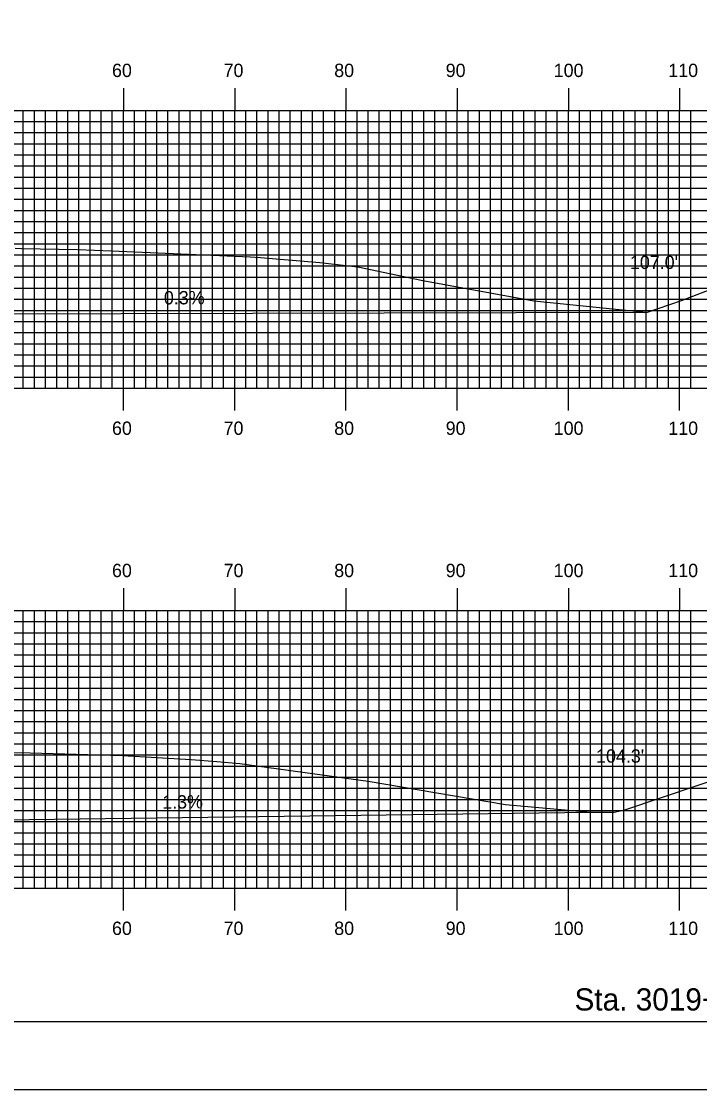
# Model space of a CAD drawing. Extents: x 1685979 to 1686323, y 461260 to 461480.
# Drawn here: x 1686196.1 to 1686257.1, y 461260 to 461356.1 of the extents above; entities that cross this region are included whole.
import ezdxf

# ---------------------------------------------------------------- set-up
doc = ezdxf.new("R2010")
doc.units = 0
for name, color, linetype in [('ANNOTATION', 7, 'Continuous'), ('BORDER', 7, 'Continuous'), ('D_Roadway_SlopeLines', 7, 'Continuous'), ('D_Text_Standard', 7, 'Continuous'), ('H_V ANNOTATION', 7, 'Continuous'), ('MAJOR', 7, 'Continuous'), ('MINOR', 7, 'Continuous'), ('PLOT BOUNDARY', 7, 'Continuous'), ('S_Roadway_Centerline', 7, 'Continuous')]:
    doc.layers.add(name, color=color, linetype=linetype)

msp = doc.modelspace()

# ---------------------------------------------------------------- linework, layer by layer
at = {"layer": 'BORDER'}
msp.add_lwpolyline([(1685995.656, 461266.072), (1686315.656, 461266.072), (1686315.656, 461476.072), (1685995.656, 461476.072)], close=True, dxfattribs=at)
at = {"layer": 'D_Roadway_SlopeLines'}
for points in [[(1686169.511, 461329.71), (1686252.38, 461329.925)], [(1686169.511, 461329.71), (1686252.38, 461329.925)], [(1686169.511, 461329.71), (1686252.38, 461329.925)], [(1686169.511, 461329.71), (1686252.38, 461329.925)], [(1686171.511, 461283.946), (1686249.53, 461284.948)], [(1686171.511, 461283.946), (1686249.53, 461284.948)], [(1686171.511, 461283.946), (1686249.53, 461284.948)], [(1686171.511, 461283.946), (1686249.53, 461284.948)]]:
    msp.add_lwpolyline(points, dxfattribs=at)
at = {"layer": 'MAJOR'}
for p, q in [((1686205.256, 461350.076), (1686205.256, 461348.072)), ((1686215.256, 461350.076), (1686215.256, 461348.072)), ((1686225.256, 461350.076), (1686225.256, 461348.072)), ((1686235.256, 461350.076), (1686235.256, 461348.072)), ((1686245.256, 461350.076), (1686245.256, 461348.072)), ((1686255.256, 461350.076), (1686255.256, 461348.072)), ((1686005.256, 461348.072), (1686285.256, 461348.072)), ((1686005.256, 461348.072), (1686285.256, 461348.072)), ((1686205.256, 461323.072), (1686205.256, 461348.072)), ((1686215.256, 461323.072), (1686215.256, 461348.072)), ((1686225.256, 461323.072), (1686225.256, 461348.072)), ((1686235.256, 461323.072), (1686235.256, 461348.072)), ((1686245.256, 461323.072), (1686245.256, 461348.072)), ((1686255.256, 461323.072), (1686255.256, 461348.072)), ((1686005.256, 461343.072), (1686285.256, 461343.072)), ((1686005.256, 461338.072), (1686285.256, 461338.072)), ((1686005.256, 461333.072), (1686285.256, 461333.072)), ((1686005.256, 461328.072), (1686285.256, 461328.072)), ((1686005.256, 461323.072), (1686285.256, 461323.072)), ((1686005.256, 461323.072), (1686285.256, 461323.072)), ((1686205.256, 461321.068), (1686205.256, 461323.072)), ((1686215.256, 461321.068), (1686215.256, 461323.072)), ((1686225.256, 461321.068), (1686225.256, 461323.072)), ((1686235.256, 461321.068), (1686235.256, 461323.072)), ((1686245.256, 461321.068), (1686245.256, 461323.072)), ((1686255.256, 461321.068), (1686255.256, 461323.072)), ((1686205.256, 461305.076), (1686205.256, 461303.072)), ((1686215.256, 461305.076), (1686215.256, 461303.072)), ((1686225.256, 461305.076), (1686225.256, 461303.072)), ((1686235.256, 461305.076), (1686235.256, 461303.072)), ((1686245.256, 461305.076), (1686245.256, 461303.072)), ((1686255.256, 461305.076), (1686255.256, 461303.072)), ((1686005.256, 461303.072), (1686285.256, 461303.072)), ((1686005.256, 461303.072), (1686285.256, 461303.072)), ((1686205.256, 461278.072), (1686205.256, 461303.072)), ((1686215.256, 461278.072), (1686215.256, 461303.072)), ((1686225.256, 461278.072), (1686225.256, 461303.072)), ((1686235.256, 461278.072), (1686235.256, 461303.072)), ((1686245.256, 461278.072), (1686245.256, 461303.072)), ((1686255.256, 461278.072), (1686255.256, 461303.072)), ((1686005.256, 461298.072), (1686285.256, 461298.072)), ((1686005.256, 461293.072), (1686285.256, 461293.072)), ((1686005.256, 461288.072), (1686285.256, 461288.072)), ((1686005.256, 461283.072), (1686285.256, 461283.072)), ((1686005.256, 461278.072), (1686285.256, 461278.072)), ((1686005.256, 461278.072), (1686285.256, 461278.072)), ((1686205.256, 461276.068), (1686205.256, 461278.072)), ((1686215.256, 461276.068), (1686215.256, 461278.072)), ((1686225.256, 461276.068), (1686225.256, 461278.072)), ((1686235.256, 461276.068), (1686235.256, 461278.072)), ((1686245.256, 461276.068), (1686245.256, 461278.072)), ((1686255.256, 461276.068), (1686255.256, 461278.072))]:
    msp.add_line(p, q, dxfattribs=at)
at = {"layer": 'MINOR'}
for p, q in [((1686196.256, 461323.072), (1686196.256, 461348.072)), ((1686197.256, 461323.072), (1686197.256, 461348.072)), ((1686198.256, 461323.072), (1686198.256, 461348.072)), ((1686199.256, 461323.072), (1686199.256, 461348.072)), ((1686200.256, 461323.072), (1686200.256, 461348.072)), ((1686201.256, 461323.072), (1686201.256, 461348.072)), ((1686202.256, 461323.072), (1686202.256, 461348.072)), ((1686203.256, 461323.072), (1686203.256, 461348.072)), ((1686204.256, 461323.072), (1686204.256, 461348.072)), ((1686206.256, 461323.072), (1686206.256, 461348.072)), ((1686207.256, 461323.072), (1686207.256, 461348.072)), ((1686208.256, 461323.072), (1686208.256, 461348.072)), ((1686209.256, 461323.072), (1686209.256, 461348.072)), ((1686210.256, 461323.072), (1686210.256, 461348.072)), ((1686211.256, 461323.072), (1686211.256, 461348.072)), ((1686212.256, 461323.072), (1686212.256, 461348.072)), ((1686213.256, 461323.072), (1686213.256, 461348.072)), ((1686214.256, 461323.072), (1686214.256, 461348.072)), ((1686216.256, 461323.072), (1686216.256, 461348.072)), ((1686217.256, 461323.072), (1686217.256, 461348.072)), ((1686218.256, 461323.072), (1686218.256, 461348.072)), ((1686219.256, 461323.072), (1686219.256, 461348.072)), ((1686220.256, 461323.072), (1686220.256, 461348.072)), ((1686221.256, 461323.072), (1686221.256, 461348.072)), ((1686222.256, 461323.072), (1686222.256, 461348.072)), ((1686223.256, 461323.072), (1686223.256, 461348.072)), ((1686224.256, 461323.072), (1686224.256, 461348.072)), ((1686226.256, 461323.072), (1686226.256, 461348.072)), ((1686227.256, 461323.072), (1686227.256, 461348.072)), ((1686228.256, 461323.072), (1686228.256, 461348.072)), ((1686229.256, 461323.072), (1686229.256, 461348.072)), ((1686230.256, 461323.072), (1686230.256, 461348.072)), ((1686231.256, 461323.072), (1686231.256, 461348.072)), ((1686232.256, 461323.072), (1686232.256, 461348.072)), ((1686233.256, 461323.072), (1686233.256, 461348.072)), ((1686234.256, 461323.072), (1686234.256, 461348.072)), ((1686236.256, 461323.072), (1686236.256, 461348.072)), ((1686237.256, 461323.072), (1686237.256, 461348.072)), ((1686238.256, 461323.072), (1686238.256, 461348.072)), ((1686239.256, 461323.072), (1686239.256, 461348.072)), ((1686240.256, 461323.072), (1686240.256, 461348.072)), ((1686241.256, 461323.072), (1686241.256, 461348.072)), ((1686242.256, 461323.072), (1686242.256, 461348.072)), ((1686243.256, 461323.072), (1686243.256, 461348.072)), ((1686244.256, 461323.072), (1686244.256, 461348.072)), ((1686246.256, 461323.072), (1686246.256, 461348.072)), ((1686247.256, 461323.072), (1686247.256, 461348.072)), ((1686248.256, 461323.072), (1686248.256, 461348.072)), ((1686249.256, 461323.072), (1686249.256, 461348.072)), ((1686250.256, 461323.072), (1686250.256, 461348.072)), ((1686251.256, 461323.072), (1686251.256, 461348.072)), ((1686252.256, 461323.072), (1686252.256, 461348.072)), ((1686253.256, 461323.072), (1686253.256, 461348.072)), ((1686254.256, 461323.072), (1686254.256, 461348.072)), ((1686256.256, 461323.072), (1686256.256, 461348.072)), ((1686005.256, 461347.072), (1686285.256, 461347.072)), ((1686005.256, 461346.072), (1686285.256, 461346.072)), ((1686005.256, 461345.072), (1686285.256, 461345.072)), ((1686005.256, 461344.072), (1686285.256, 461344.072)), ((1686005.256, 461342.072), (1686285.256, 461342.072)), ((1686005.256, 461341.072), (1686285.256, 461341.072)), ((1686005.256, 461340.072), (1686285.256, 461340.072)), ((1686005.256, 461339.072), (1686285.256, 461339.072)), ((1686005.256, 461337.072), (1686285.256, 461337.072)), ((1686005.256, 461336.072), (1686285.256, 461336.072)), ((1686005.256, 461335.072), (1686285.256, 461335.072)), ((1686005.256, 461334.072), (1686285.256, 461334.072)), ((1686005.256, 461332.072), (1686285.256, 461332.072)), ((1686005.256, 461331.072), (1686285.256, 461331.072)), ((1686005.256, 461330.072), (1686285.256, 461330.072)), ((1686005.256, 461329.072), (1686285.256, 461329.072)), ((1686005.256, 461327.072), (1686285.256, 461327.072)), ((1686005.256, 461326.072), (1686285.256, 461326.072)), ((1686005.256, 461325.072), (1686285.256, 461325.072)), ((1686005.256, 461324.072), (1686285.256, 461324.072)), ((1686196.256, 461278.072), (1686196.256, 461303.072)), ((1686197.256, 461278.072), (1686197.256, 461303.072)), ((1686198.256, 461278.072), (1686198.256, 461303.072)), ((1686199.256, 461278.072), (1686199.256, 461303.072)), ((1686200.256, 461278.072), (1686200.256, 461303.072)), ((1686201.256, 461278.072), (1686201.256, 461303.072)), ((1686202.256, 461278.072), (1686202.256, 461303.072)), ((1686203.256, 461278.072), (1686203.256, 461303.072)), ((1686204.256, 461278.072), (1686204.256, 461303.072)), ((1686206.256, 461278.072), (1686206.256, 461303.072)), ((1686207.256, 461278.072), (1686207.256, 461303.072)), ((1686208.256, 461278.072), (1686208.256, 461303.072)), ((1686209.256, 461278.072), (1686209.256, 461303.072)), ((1686210.256, 461278.072), (1686210.256, 461303.072)), ((1686211.256, 461278.072), (1686211.256, 461303.072)), ((1686212.256, 461278.072), (1686212.256, 461303.072)), ((1686213.256, 461278.072), (1686213.256, 461303.072)), ((1686214.256, 461278.072), (1686214.256, 461303.072)), ((1686216.256, 461278.072), (1686216.256, 461303.072)), ((1686217.256, 461278.072), (1686217.256, 461303.072)), ((1686218.256, 461278.072), (1686218.256, 461303.072)), ((1686219.256, 461278.072), (1686219.256, 461303.072)), ((1686220.256, 461278.072), (1686220.256, 461303.072)), ((1686221.256, 461278.072), (1686221.256, 461303.072)), ((1686222.256, 461278.072), (1686222.256, 461303.072)), ((1686223.256, 461278.072), (1686223.256, 461303.072)), ((1686224.256, 461278.072), (1686224.256, 461303.072)), ((1686226.256, 461278.072), (1686226.256, 461303.072)), ((1686227.256, 461278.072), (1686227.256, 461303.072)), ((1686228.256, 461278.072), (1686228.256, 461303.072)), ((1686229.256, 461278.072), (1686229.256, 461303.072)), ((1686230.256, 461278.072), (1686230.256, 461303.072)), ((1686231.256, 461278.072), (1686231.256, 461303.072)), ((1686232.256, 461278.072), (1686232.256, 461303.072)), ((1686233.256, 461278.072), (1686233.256, 461303.072)), ((1686234.256, 461278.072), (1686234.256, 461303.072)), ((1686236.256, 461278.072), (1686236.256, 461303.072)), ((1686237.256, 461278.072), (1686237.256, 461303.072)), ((1686238.256, 461278.072), (1686238.256, 461303.072)), ((1686239.256, 461278.072), (1686239.256, 461303.072)), ((1686240.256, 461278.072), (1686240.256, 461303.072)), ((1686241.256, 461278.072), (1686241.256, 461303.072)), ((1686242.256, 461278.072), (1686242.256, 461303.072)), ((1686243.256, 461278.072), (1686243.256, 461303.072)), ((1686244.256, 461278.072), (1686244.256, 461303.072)), ((1686246.256, 461278.072), (1686246.256, 461303.072)), ((1686247.256, 461278.072), (1686247.256, 461303.072)), ((1686248.256, 461278.072), (1686248.256, 461303.072)), ((1686249.256, 461278.072), (1686249.256, 461303.072)), ((1686250.256, 461278.072), (1686250.256, 461303.072)), ((1686251.256, 461278.072), (1686251.256, 461303.072)), ((1686252.256, 461278.072), (1686252.256, 461303.072)), ((1686253.256, 461278.072), (1686253.256, 461303.072)), ((1686254.256, 461278.072), (1686254.256, 461303.072)), ((1686256.256, 461278.072), (1686256.256, 461303.072)), ((1686005.256, 461302.072), (1686285.256, 461302.072)), ((1686005.256, 461301.072), (1686285.256, 461301.072)), ((1686005.256, 461300.072), (1686285.256, 461300.072)), ((1686005.256, 461299.072), (1686285.256, 461299.072)), ((1686005.256, 461297.072), (1686285.256, 461297.072)), ((1686005.256, 461296.072), (1686285.256, 461296.072)), ((1686005.256, 461295.072), (1686285.256, 461295.072)), ((1686005.256, 461294.072), (1686285.256, 461294.072)), ((1686005.256, 461292.072), (1686285.256, 461292.072)), ((1686005.256, 461291.072), (1686285.256, 461291.072)), ((1686005.256, 461290.072), (1686285.256, 461290.072)), ((1686005.256, 461289.072), (1686285.256, 461289.072)), ((1686005.256, 461287.072), (1686285.256, 461287.072)), ((1686005.256, 461286.072), (1686285.256, 461286.072)), ((1686005.256, 461285.072), (1686285.256, 461285.072)), ((1686005.256, 461284.072), (1686285.256, 461284.072)), ((1686005.256, 461282.072), (1686285.256, 461282.072)), ((1686005.256, 461281.072), (1686285.256, 461281.072)), ((1686005.256, 461280.072), (1686285.256, 461280.072)), ((1686005.256, 461279.072), (1686285.256, 461279.072))]:
    msp.add_line(p, q, dxfattribs=at)
at = {"layer": 'PLOT BOUNDARY'}
msp.add_lwpolyline([(1685979.469, 461259.954), (1686319.469, 461259.954), (1686319.469, 461479.954), (1685979.469, 461479.954)], close=True, dxfattribs=at)
at = {"layer": 'S_Roadway_Centerline'}
for points in [[(1686195.53, 461335.674), (1686196.087, 461335.655), (1686201.117, 461335.556), (1686204.194, 461335.445), (1686216.635, 461334.899), (1686217.586, 461334.832), (1686222.925, 461334.374), (1686226.327, 461333.983), (1686232.17, 461332.753), (1686242.158, 461330.937), (1686249.83, 461330.155), (1686252.243, 461329.899), (1686252.281, 461329.891), (1686255.431, 461330.978), (1686260.041, 461332.736)], [(1686193.611, 461290.316), (1686196.862, 461290.273), (1686205.165, 461290.007), (1686211.339, 461289.648), (1686213.64, 461289.492), (1686215.705, 461289.307), (1686227.266, 461287.721), (1686239.612, 461285.615), (1686247.279, 461284.912), (1686249.358, 461284.907), (1686250.337, 461285.142), (1686260.318, 461288.499)]]:
    msp.add_lwpolyline(points, dxfattribs=at)

# ---------------------------------------------------------------- texts
at = {"layer": 'ANNOTATION'}
for s, rotation, p in [('0.3%', 0.14909, (1686208.896, 461330.612)), ('1.3%', 0.73585, (1686208.75, 461285.225))]:
    msp.add_text(s, height=1.2, rotation=rotation, dxfattribs=at).set_placement(p)
at = {"layer": 'D_Text_Standard'}
for s, p in [("107.0'", (1686250.79, 461333.798)), ("104.3'", (1686247.748, 461289.377))]:
    msp.add_text(s, height=1.2, dxfattribs=at).set_placement(p)
at = {"layer": 'H_V ANNOTATION'}
for s, height, p in [('60', 1.2, (1686204.228, 461351.072)), ('70', 1.2, (1686214.26, 461351.072)), ('80', 1.2, (1686224.206, 461351.072)), ('90', 1.2, (1686234.228, 461351.072)), ('100', 1.2, (1686243.939, 461351.072)), ('110', 1.2, (1686254.239, 461351.072)), ('60', 1.2, (1686204.228, 461318.872)), ('70', 1.2, (1686214.26, 461318.872)), ('80', 1.2, (1686224.206, 461318.872)), ('90', 1.2, (1686234.228, 461318.872)), ('100', 1.2, (1686243.939, 461318.872)), ('110', 1.2, (1686254.239, 461318.872)), ('60', 1.2, (1686204.228, 461306.072)), ('70', 1.2, (1686214.26, 461306.072)), ('80', 1.2, (1686224.206, 461306.072)), ('90', 1.2, (1686234.228, 461306.072)), ('100', 1.2, (1686243.939, 461306.072)), ('110', 1.2, (1686254.239, 461306.072)), ('60', 1.2, (1686204.228, 461273.872)), ('70', 1.2, (1686214.26, 461273.872)), ('80', 1.2, (1686224.206, 461273.872)), ('90', 1.2, (1686234.228, 461273.872)), ('100', 1.2, (1686243.939, 461273.872)), ('110', 1.2, (1686254.239, 461273.872)), ('Sta. 3019+00.00 to Sta. 3020+50.00', 2.0004, (1686245.808, 461267.072))]:
    msp.add_text(s, height=height, dxfattribs=at).set_placement(p)

doc.saveas('drawing.dxf')
